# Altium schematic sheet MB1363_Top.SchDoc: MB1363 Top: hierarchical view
size A4; Date: Not used; ApprovedBy: Not used; CheckedBy: Not used; Author: Not used; CompanyName: STMicroelectronics; DrawnBy: Not used; Engineer: Not used; Organization: Not used; Address1: Not used; Address2: Not used; Address3: Not used; Address4: Not used; DocumentNumber: 2; Revision: Not used; SheetNumber: 2; SheetTotal: 9
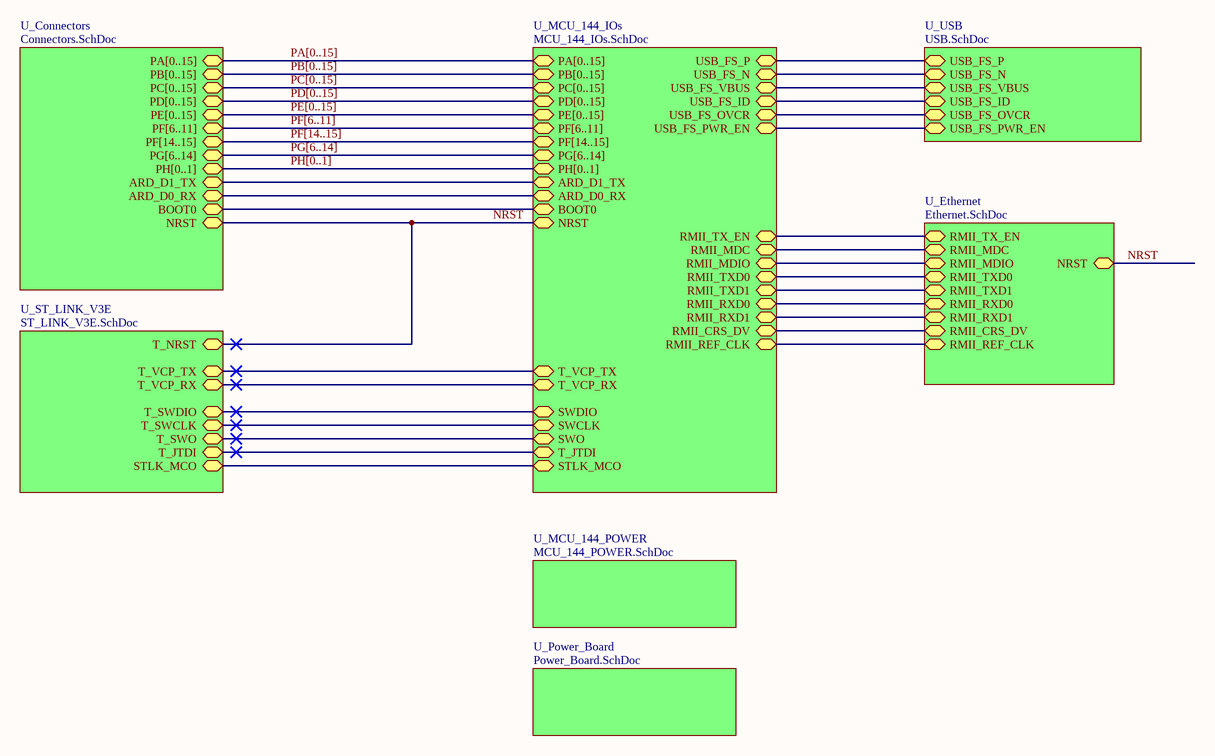
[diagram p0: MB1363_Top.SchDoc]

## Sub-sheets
U_Connectors = Connectors.SchDoc: PA[0..15] (bidir), PB[0..15] (bidir), PC[0..15] (bidir), NRST (bidir), PD[0..15] (bidir), PE[0..15] (bidir), PF[6..11] (bidir), PG[6..14] (bidir), PH[0..1] (bidir), BOOT0 (bidir), PF[14..15] (bidir), ARD_D1_TX (bidir), ARD_D0_RX (bidir)
U_Ethernet = Ethernet.SchDoc: RMII_CRS_DV (bidir), RMII_REF_CLK (bidir), RMII_TXD0 (bidir), RMII_RXD0 (bidir), RMII_TX_EN (bidir), NRST (bidir), RMII_RXD1 (bidir), RMII_MDC (bidir), RMII_TXD1 (bidir), RMII_MDIO (bidir)
U_MCU_144_IOs = MCU_144_IOs.SchDoc: NRST (bidir), BOOT0 (bidir), SWO (bidir), STLK_MCO (bidir), SWCLK (bidir), SWDIO (bidir), RMII_TX_EN (bidir), RMII_MDC (bidir), RMII_TXD0 (bidir), RMII_TXD1 (bidir), RMII_REF_CLK (bidir), RMII_RXD1 (bidir), RMII_MDIO (bidir), RMII_CRS_DV (bidir), RMII_RXD0 (bidir), USB_FS_N (bidir), USB_FS_P (bidir), USB_FS_OVCR (bidir), USB_FS_PWR_EN (bidir), USB_FS_VBUS (bidir), USB_FS_ID (bidir), T_VCP_TX (bidir), T_VCP_RX (bidir), PA[0..15] (bidir), PB[0..15] (bidir), PC[0..15] (bidir), PD[0..15] (bidir), PE[0..15] (bidir), PF[6..11] (bidir), PG[6..14] (bidir), PH[0..1] (bidir), PF[14..15] (bidir), ARD_D1_TX (bidir), ARD_D0_RX (bidir), T_JTDI (bidir)
U_MCU_144_POWER = MCU_144_POWER.SchDoc: no entries
U_Power_Board = Power_Board.SchDoc: no entries
U_ST_LINK_V3E = ST_LINK_V3E.SchDoc: T_NRST (bidir), STLK_MCO (bidir), T_SWDIO (bidir), T_VCP_TX (bidir), T_VCP_RX (bidir), T_SWCLK (bidir), T_SWO (bidir), T_JTDI (bidir)
U_USB = USB.SchDoc: USB_FS_N (bidir), USB_FS_P (bidir), USB_FS_OVCR (bidir), USB_FS_PWR_EN (bidir), USB_FS_VBUS (bidir), USB_FS_ID (bidir)

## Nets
NRST: sheet U_Connectors/NRST, sheet U_MCU_144_IOs/NRST, sheet U_Ethernet/NRST, sheet U_ST_LINK_V3E/T_NRST
(unnamed): sheet U_Connectors/BOOT0, sheet U_MCU_144_IOs/BOOT0
(unnamed): sheet U_Connectors/ARD_D1_TX, sheet U_MCU_144_IOs/ARD_D1_TX  [a separate net that carries the same name]
(unnamed): sheet U_Connectors/ARD_D0_RX, sheet U_MCU_144_IOs/ARD_D0_RX  [a separate net that carries the same name]
(unnamed): sheet U_MCU_144_IOs/SWO, sheet U_ST_LINK_V3E/T_SWO  [a separate net that carries the same name]
(unnamed): sheet U_MCU_144_IOs/STLK_MCO, sheet U_ST_LINK_V3E/STLK_MCO  [a separate net that carries the same name]
(unnamed): sheet U_MCU_144_IOs/SWCLK, sheet U_ST_LINK_V3E/T_SWCLK  [a separate net that carries the same name]
(unnamed): sheet U_MCU_144_IOs/SWDIO, sheet U_ST_LINK_V3E/T_SWDIO  [a separate net that carries the same name]
(unnamed): sheet U_MCU_144_IOs/RMII_TX_EN, sheet U_Ethernet/RMII_TX_EN  [a separate net that carries the same name]
(unnamed): sheet U_MCU_144_IOs/RMII_MDC, sheet U_Ethernet/RMII_MDC  [a separate net that carries the same name]
(unnamed): sheet U_MCU_144_IOs/RMII_TXD0, sheet U_Ethernet/RMII_TXD0  [a separate net that carries the same name]
(unnamed): sheet U_MCU_144_IOs/RMII_TXD1, sheet U_Ethernet/RMII_TXD1  [a separate net that carries the same name]
(unnamed): sheet U_MCU_144_IOs/RMII_REF_CLK, sheet U_Ethernet/RMII_REF_CLK  [a separate net that carries the same name]
(unnamed): sheet U_MCU_144_IOs/RMII_RXD1, sheet U_Ethernet/RMII_RXD1  [a separate net that carries the same name]
(unnamed): sheet U_MCU_144_IOs/RMII_MDIO, sheet U_Ethernet/RMII_MDIO  [a separate net that carries the same name]
(unnamed): sheet U_MCU_144_IOs/RMII_CRS_DV, sheet U_Ethernet/RMII_CRS_DV  [a separate net that carries the same name]
(unnamed): sheet U_MCU_144_IOs/RMII_RXD0, sheet U_Ethernet/RMII_RXD0  [a separate net that carries the same name]
(unnamed): sheet U_MCU_144_IOs/USB_FS_N, sheet U_USB/USB_FS_N  [a separate net that carries the same name]
(unnamed): sheet U_MCU_144_IOs/USB_FS_P, sheet U_USB/USB_FS_P  [a separate net that carries the same name]
(unnamed): sheet U_MCU_144_IOs/USB_FS_OVCR, sheet U_USB/USB_FS_OVCR  [a separate net that carries the same name]
(unnamed): sheet U_MCU_144_IOs/USB_FS_PWR_EN, sheet U_USB/USB_FS_PWR_EN  [a separate net that carries the same name]
(unnamed): sheet U_MCU_144_IOs/USB_FS_VBUS, sheet U_USB/USB_FS_VBUS  [a separate net that carries the same name]
(unnamed): sheet U_MCU_144_IOs/USB_FS_ID, sheet U_USB/USB_FS_ID  [a separate net that carries the same name]
(unnamed): sheet U_MCU_144_IOs/T_VCP_TX, sheet U_ST_LINK_V3E/T_VCP_TX  [a separate net that carries the same name]
(unnamed): sheet U_MCU_144_IOs/T_VCP_RX, sheet U_ST_LINK_V3E/T_VCP_RX  [a separate net that carries the same name]
(unnamed): sheet U_MCU_144_IOs/T_JTDI, sheet U_ST_LINK_V3E/T_JTDI  [a separate net that carries the same name]

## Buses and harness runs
bus PA[0..15] = sheet U_Connectors/PA[0..15] = sheet U_MCU_144_IOs/PA[0..15]
bus PB[0..15] = sheet U_Connectors/PB[0..15] = sheet U_MCU_144_IOs/PB[0..15]
bus PC[0..15] = sheet U_Connectors/PC[0..15] = sheet U_MCU_144_IOs/PC[0..15]
bus PD[0..15] = sheet U_Connectors/PD[0..15] = sheet U_MCU_144_IOs/PD[0..15]
bus PE[0..15] = sheet U_Connectors/PE[0..15] = sheet U_MCU_144_IOs/PE[0..15]
bus PF[6..11] = sheet U_Connectors/PF[6..11] = sheet U_MCU_144_IOs/PF[6..11]
bus PF[14..15] = sheet U_Connectors/PF[14..15] = sheet U_MCU_144_IOs/PF[14..15]
bus PG[6..14] = sheet U_Connectors/PG[6..14] = sheet U_MCU_144_IOs/PG[6..14]
bus PH[0..1] = sheet U_Connectors/PH[0..1] = sheet U_MCU_144_IOs/PH[0..1]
